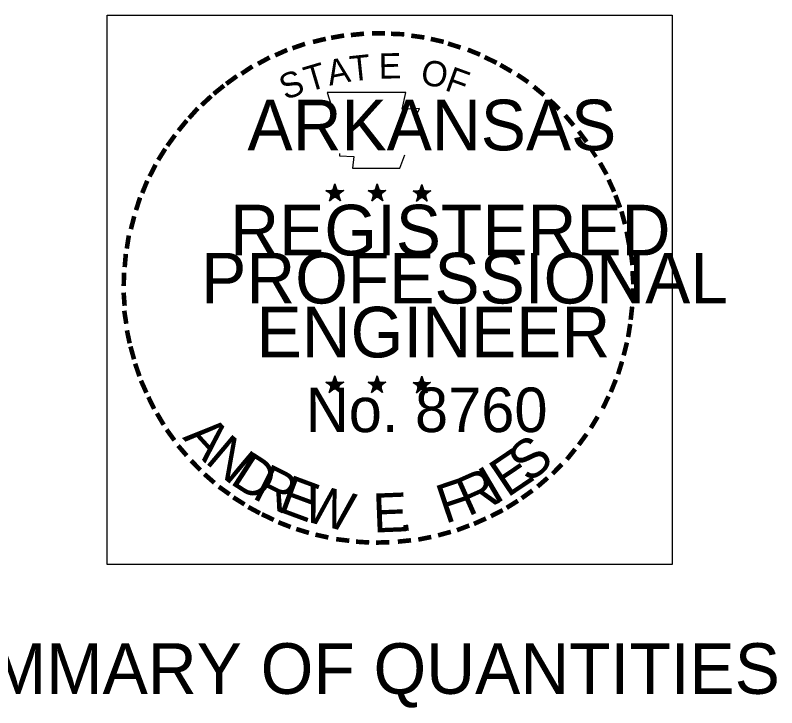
# Model space of a CAD drawing. Extents: x 1226603 to 1228117, y 151305 to 152343.
# Drawn here: x 1227929.3 to 1228117.2, y 151304.9 to 151475.9 of the extents above; entities that cross this region are included whole.
import ezdxf

# ---------------------------------------------------------------- set-up
doc = ezdxf.new("R2010")
doc.units = 0
for name, color, linetype in [('R_Border Notes', 7, 'Continuous'), ('R_Border PE', 7, 'Continuous'), ('R_Border Prem', 7, 'Continuous')]:
    doc.layers.add(name, color=color, linetype=linetype)

msp = doc.modelspace()

# ---------------------------------------------------------------- linework, layer by layer
at = {"layer": 'R_Border PE'}
for p, q in [((1228008.15, 151434.21), (1228007.83, 151432.64)), ((1228008.15, 151434.21), (1228007.9, 151432.58)), ((1228008.15, 151434.21), (1228008.08, 151432.64)), ((1228008.15, 151431.89), (1228008.15, 151434.21)), ((1228008.15, 151434.21), (1228008.58, 151432.58)), ((1228008.15, 151434.21), (1228008.46, 151432.64)), ((1228008.15, 151434.21), (1228008.33, 151432.64)), ((1228018.58, 151434.21), (1228018.27, 151432.64)), ((1228018.58, 151434.21), (1228018.33, 151432.58)), ((1228018.58, 151434.21), (1228018.46, 151432.64)), ((1228018.58, 151431.89), (1228018.58, 151434.21)), ((1228018.58, 151434.21), (1228019.02, 151432.58)), ((1228018.58, 151434.21), (1228018.9, 151432.64)), ((1228018.58, 151434.21), (1228018.71, 151432.64)), ((1228029.65, 151434.08), (1228029.27, 151432.58)), ((1228029.65, 151434.08), (1228029.4, 151432.52)), ((1228029.65, 151434.08), (1228029.52, 151432.52)), ((1228029.65, 151431.83), (1228029.65, 151434.08)), ((1228029.65, 151434.08), (1228030.08, 151432.52)), ((1228029.65, 151434.08), (1228029.96, 151432.52)), ((1228029.65, 151434.08), (1228029.77, 151432.58)), ((1228005.96, 151432.58), (1228008.15, 151431.89)), ((1228005.96, 151432.58), (1228007.58, 151432.46)), ((1228005.96, 151432.58), (1228007.58, 151432.33)), ((1228005.96, 151432.58), (1228007.52, 151432.21)), ((1228005.96, 151432.58), (1228007.52, 151431.96)), ((1228005.96, 151432.58), (1228007.46, 151431.83)), ((1228005.96, 151432.58), (1228007.46, 151431.71)), ((1228006.83, 151430.02), (1228008.15, 151431.89)), ((1228010.33, 151432.58), (1228008.15, 151431.89)), ((1228009.52, 151430.02), (1228008.15, 151431.89)), ((1228010.33, 151432.58), (1228008.4, 151432.46)), ((1228010.33, 151432.58), (1228008.52, 151432.27)), ((1228010.33, 151432.58), (1228008.52, 151432.14)), ((1228009.52, 151430.02), (1228008.77, 151431.89)), ((1228010.33, 151432.58), (1228008.96, 151432.02)), ((1228010.33, 151432.58), (1228009.08, 151431.96)), ((1228010.33, 151432.58), (1228009.15, 151431.89)), ((1228016.4, 151432.58), (1228018.58, 151431.89)), ((1228016.4, 151432.58), (1228018.02, 151432.46)), ((1228016.4, 151432.58), (1228018.02, 151432.33)), ((1228016.4, 151432.58), (1228017.96, 151432.21)), ((1228016.4, 151432.58), (1228017.9, 151431.96)), ((1228016.4, 151432.58), (1228017.9, 151431.83)), ((1228016.4, 151432.58), (1228017.9, 151431.71)), ((1228017.27, 151430.02), (1228018.58, 151431.89)), ((1228020.77, 151432.58), (1228018.58, 151431.89)), ((1228019.96, 151430.02), (1228018.58, 151431.89)), ((1228020.77, 151432.58), (1228018.83, 151432.46)), ((1228020.77, 151432.58), (1228018.96, 151432.27)), ((1228020.77, 151432.58), (1228018.96, 151432.14)), ((1228019.96, 151430.02), (1228019.21, 151431.89)), ((1228020.77, 151432.58), (1228019.4, 151432.02)), ((1228020.77, 151432.58), (1228019.52, 151431.96)), ((1228020.77, 151432.58), (1228019.58, 151431.89)), ((1228027.46, 151432.52), (1228029.65, 151431.83)), ((1228027.46, 151432.52), (1228029.08, 151432.33)), ((1228027.46, 151432.52), (1228029.02, 151432.21)), ((1228027.46, 151432.52), (1228029.02, 151432.14)), ((1228027.46, 151432.52), (1228028.96, 151431.89)), ((1228027.46, 151432.52), (1228028.96, 151431.77)), ((1228027.46, 151432.52), (1228028.96, 151431.64)), ((1228031.83, 151432.52), (1228029.65, 151431.83)), ((1228031.83, 151432.52), (1228029.9, 151432.39)), ((1228031.83, 151432.52), (1228030.02, 151432.21)), ((1228031.83, 151432.52), (1228030.02, 151432.08)), ((1228031.83, 151432.52), (1228030.46, 151431.96)), ((1228031.83, 151432.52), (1228030.52, 151431.89)), ((1228031.83, 151432.52), (1228030.65, 151431.83)), ((1228006.83, 151430.02), (1228007.52, 151431.77)), ((1228006.83, 151430.02), (1228007.58, 151431.58)), ((1228006.83, 151430.02), (1228007.71, 151431.52)), ((1228006.83, 151430.02), (1228008.15, 151431.39)), ((1228006.83, 151430.02), (1228007.9, 151431.33)), ((1228006.83, 151430.02), (1228008.21, 151431.21)), ((1228009.52, 151430.02), (1228008.15, 151431.39)), ((1228009.52, 151430.02), (1228008.15, 151431.21)), ((1228009.52, 151430.02), (1228008.4, 151431.33)), ((1228009.52, 151430.02), (1228008.58, 151431.58)), ((1228009.52, 151430.02), (1228008.65, 151431.83)), ((1228017.27, 151430.02), (1228017.96, 151431.77)), ((1228017.27, 151430.02), (1228018.02, 151431.58)), ((1228017.27, 151430.02), (1228018.15, 151431.52)), ((1228017.27, 151430.02), (1228018.58, 151431.39)), ((1228017.27, 151430.02), (1228018.33, 151431.33)), ((1228017.27, 151430.02), (1228018.65, 151431.21)), ((1228019.96, 151430.02), (1228018.58, 151431.39)), ((1228019.96, 151430.02), (1228018.58, 151431.21)), ((1228019.96, 151430.02), (1228018.83, 151431.33)), ((1228019.96, 151430.02), (1228019.02, 151431.58)), ((1228019.96, 151430.02), (1228019.08, 151431.83)), ((1228028.27, 151429.96), (1228029.65, 151431.83)), ((1228028.27, 151429.96), (1228029.02, 151431.71)), ((1228028.27, 151429.96), (1228029.08, 151431.52)), ((1228028.27, 151429.96), (1228029.21, 151431.46)), ((1228028.27, 151429.96), (1228029.65, 151431.33)), ((1228028.27, 151429.96), (1228029.4, 151431.27)), ((1228028.27, 151429.96), (1228029.71, 151431.14)), ((1228030.96, 151429.96), (1228029.65, 151431.83)), ((1228030.96, 151429.96), (1228029.65, 151431.33)), ((1228030.96, 151429.96), (1228029.65, 151431.14)), ((1228030.96, 151429.96), (1228029.9, 151431.27)), ((1228030.96, 151429.96), (1228030.08, 151431.52)), ((1228030.96, 151429.96), (1228030.15, 151431.77)), ((1228030.96, 151429.96), (1228030.27, 151431.77)), ((1228008.15, 151386.83), (1228007.77, 151385.33)), ((1228008.15, 151386.83), (1228007.9, 151385.27)), ((1228008.15, 151386.83), (1228008.02, 151385.27)), ((1228008.15, 151384.58), (1228008.15, 151386.83)), ((1228008.15, 151386.83), (1228008.58, 151385.27)), ((1228008.15, 151386.83), (1228008.46, 151385.27)), ((1228008.15, 151386.83), (1228008.27, 151385.27)), ((1228018.58, 151386.83), (1228018.21, 151385.33)), ((1228018.58, 151386.83), (1228018.33, 151385.27)), ((1228018.58, 151386.83), (1228018.46, 151385.27)), ((1228018.58, 151384.58), (1228018.58, 151386.83)), ((1228018.58, 151386.83), (1228018.96, 151385.27)), ((1228018.58, 151386.83), (1228018.9, 151385.27)), ((1228018.58, 151386.83), (1228018.71, 151385.27)), ((1228029.65, 151386.77), (1228029.27, 151385.21)), ((1228029.65, 151386.77), (1228029.4, 151385.21)), ((1228029.65, 151386.77), (1228029.52, 151385.21)), ((1228029.65, 151384.52), (1228029.65, 151386.77)), ((1228029.65, 151386.77), (1228030.02, 151385.21)), ((1228029.65, 151386.77), (1228029.96, 151385.21)), ((1228029.65, 151386.77), (1228029.77, 151385.21)), ((1228005.96, 151385.27), (1228008.15, 151384.58)), ((1228005.96, 151385.27), (1228007.58, 151385.08)), ((1228005.96, 151385.27), (1228007.52, 151384.96)), ((1228005.96, 151385.27), (1228007.52, 151384.89)), ((1228005.96, 151385.27), (1228007.46, 151384.64)), ((1228005.96, 151385.27), (1228007.46, 151384.52)), ((1228005.96, 151385.27), (1228007.46, 151384.39)), ((1228010.33, 151385.27), (1228008.15, 151384.58)), ((1228010.33, 151385.27), (1228008.4, 151385.14)), ((1228010.33, 151385.27), (1228008.52, 151384.96)), ((1228010.33, 151385.27), (1228008.52, 151384.83)), ((1228010.33, 151385.27), (1228008.9, 151384.71)), ((1228010.33, 151385.27), (1228009.02, 151384.64)), ((1228010.33, 151385.27), (1228009.15, 151384.52)), ((1228016.4, 151385.27), (1228018.58, 151384.58)), ((1228016.4, 151385.27), (1228017.96, 151385.08)), ((1228016.4, 151385.27), (1228017.96, 151384.96)), ((1228016.4, 151385.27), (1228017.96, 151384.89)), ((1228016.4, 151385.27), (1228017.9, 151384.64)), ((1228016.4, 151385.27), (1228017.9, 151384.52)), ((1228016.4, 151385.27), (1228017.9, 151384.39)), ((1228020.71, 151385.27), (1228018.58, 151384.58)), ((1228020.71, 151385.27), (1228018.83, 151385.14)), ((1228020.71, 151385.27), (1228018.96, 151384.96)), ((1228020.71, 151385.27), (1228018.96, 151384.83)), ((1228020.71, 151385.27), (1228019.33, 151384.71)), ((1228020.71, 151385.27), (1228019.46, 151384.64)), ((1228020.71, 151385.27), (1228019.58, 151384.52)), ((1228027.46, 151385.21), (1228029.65, 151384.52)), ((1228027.46, 151385.21), (1228029.02, 151385.02)), ((1228027.46, 151385.21), (1228029.02, 151384.89)), ((1228027.46, 151385.21), (1228028.96, 151384.77)), ((1228027.46, 151385.21), (1228028.96, 151384.58)), ((1228027.46, 151385.21), (1228028.9, 151384.39)), ((1228027.46, 151385.21), (1228028.9, 151384.27)), ((1228031.77, 151385.21), (1228029.65, 151384.52)), ((1228031.77, 151385.21), (1228029.9, 151385.08)), ((1228031.77, 151385.21), (1228030.02, 151384.89)), ((1228031.77, 151385.21), (1228030.02, 151384.77)), ((1228031.77, 151385.21), (1228030.4, 151384.64)), ((1228031.77, 151385.21), (1228030.52, 151384.52)), ((1228031.77, 151385.21), (1228030.58, 151384.46)), ((1228006.77, 151382.71), (1228008.15, 151384.58)), ((1228006.77, 151382.71), (1228007.52, 151384.46)), ((1228006.77, 151382.71), (1228007.58, 151384.21)), ((1228006.77, 151382.71), (1228007.71, 151384.14)), ((1228006.77, 151382.71), (1228008.15, 151384.08)), ((1228006.77, 151382.71), (1228007.9, 151384.02)), ((1228006.77, 151382.71), (1228008.15, 151383.89)), ((1228009.46, 151382.71), (1228008.08, 151383.89)), ((1228009.46, 151382.71), (1228008.15, 151384.58)), ((1228009.46, 151382.71), (1228008.15, 151384.02)), ((1228009.46, 151382.71), (1228008.33, 151384.02)), ((1228009.46, 151382.71), (1228008.58, 151384.52)), ((1228009.46, 151382.71), (1228008.58, 151384.27)), ((1228009.46, 151382.71), (1228008.77, 151384.52)), ((1228017.21, 151382.71), (1228018.58, 151384.58)), ((1228017.21, 151382.71), (1228017.96, 151384.46)), ((1228017.21, 151382.71), (1228018.02, 151384.21)), ((1228017.21, 151382.71), (1228018.15, 151384.14)), ((1228017.21, 151382.71), (1228018.58, 151384.08)), ((1228017.21, 151382.71), (1228018.33, 151384.02)), ((1228017.21, 151382.71), (1228018.58, 151383.89)), ((1228019.9, 151382.71), (1228018.52, 151383.89)), ((1228019.9, 151382.71), (1228018.58, 151384.58)), ((1228019.9, 151382.71), (1228018.58, 151384.02)), ((1228019.9, 151382.71), (1228018.77, 151384.02)), ((1228019.9, 151382.71), (1228019.02, 151384.52)), ((1228019.9, 151382.71), (1228019.02, 151384.27)), ((1228019.9, 151382.71), (1228019.21, 151384.52)), ((1228028.27, 151382.64), (1228029.65, 151384.52)), ((1228028.27, 151382.64), (1228028.96, 151384.39)), ((1228028.27, 151382.64), (1228029.02, 151384.14)), ((1228028.27, 151382.64), (1228029.21, 151384.08)), ((1228028.27, 151382.64), (1228029.4, 151383.96)), ((1228028.27, 151382.64), (1228029.58, 151383.96)), ((1228028.27, 151382.64), (1228029.65, 151383.83)), ((1228030.96, 151382.64), (1228029.58, 151383.96)), ((1228030.96, 151382.64), (1228029.58, 151383.77)), ((1228030.96, 151382.64), (1228029.65, 151384.52)), ((1228030.96, 151382.64), (1228029.83, 151383.96)), ((1228030.96, 151382.64), (1228030.02, 151384.14)), ((1228030.96, 151382.64), (1228030.08, 151384.46)), ((1228030.96, 151382.64), (1228030.21, 151384.46))]:
    msp.add_line(p, q, dxfattribs=at)
for points in [[(1228006.27, 151456.83), (1228007.9, 151451.64)], [(1228028.21, 151451.08), (1228029.08, 151452.83), (1228024.77, 151452.71), (1228025.71, 151456.83), (1228006.27, 151456.83)], [(1228009.33, 151441.71), (1228009.33, 151441.14), (1228012.83, 151441.02), (1228012.52, 151438.08), (1228024.21, 151438.08), (1228025.46, 151441.39)], [(1228008.15, 151434.21), (1228009.52, 151430.02), (1228005.96, 151432.58), (1228010.33, 151432.58), (1228006.83, 151430.02), (1228008.15, 151434.21)], [(1228018.58, 151434.21), (1228019.96, 151430.02), (1228016.4, 151432.58), (1228020.77, 151432.58), (1228017.27, 151430.02), (1228018.58, 151434.21)], [(1228029.65, 151434.08), (1228030.96, 151429.96), (1228027.46, 151432.52), (1228031.83, 151432.52), (1228028.27, 151429.96), (1228029.65, 151434.08)], [(1228008.15, 151386.83), (1228009.46, 151382.71), (1228005.96, 151385.27), (1228010.33, 151385.27), (1228006.77, 151382.71), (1228008.15, 151386.83)], [(1228018.58, 151386.83), (1228019.9, 151382.71), (1228016.4, 151385.27), (1228020.71, 151385.27), (1228017.21, 151382.71), (1228018.58, 151386.83)], [(1228029.65, 151386.77), (1228030.96, 151382.64), (1228027.46, 151385.21), (1228031.77, 151385.21), (1228028.27, 151382.64), (1228029.65, 151386.77)]]:
    msp.add_lwpolyline(points, dxfattribs=at)
for centre, radius in [((1228008.17, 151431.89), 1.08), ((1228008.17, 151431.89), 0.975), ((1228008.17, 151431.89), 0.904), ((1228008.17, 151431.89), 0.83), ((1228008.17, 151431.89), 0.723), ((1228008.17, 151431.89), 0.672), ((1228008.17, 151431.89), 0.619), ((1228008.17, 151431.89), 0.533), ((1228008.17, 151431.89), 0.467), ((1228008.17, 151431.89), 0.388), ((1228008.17, 151431.89), 0.31), ((1228008.17, 151431.89), 0.231), ((1228008.17, 151431.89), 0.185), ((1228008.17, 151431.89), 0.0901), ((1228018.6, 151431.89), 1.08), ((1228018.6, 151431.89), 0.975), ((1228018.6, 151431.89), 0.904), ((1228018.6, 151431.89), 0.83), ((1228018.6, 151431.89), 0.723), ((1228018.6, 151431.89), 0.672), ((1228018.6, 151431.89), 0.619), ((1228018.6, 151431.89), 0.533), ((1228018.6, 151431.89), 0.467), ((1228018.6, 151431.89), 0.388), ((1228018.6, 151431.89), 0.31), ((1228018.6, 151431.89), 0.231), ((1228018.6, 151431.89), 0.185), ((1228018.6, 151431.89), 0.0901), ((1228029.64, 151431.81), 1.08), ((1228029.64, 151431.81), 0.975), ((1228029.64, 151431.81), 0.904), ((1228029.64, 151431.81), 0.83), ((1228029.64, 151431.81), 0.723), ((1228029.64, 151431.81), 0.672), ((1228029.64, 151431.81), 0.619), ((1228029.64, 151431.81), 0.533), ((1228029.64, 151431.81), 0.467), ((1228029.64, 151431.81), 0.388), ((1228029.64, 151431.81), 0.31), ((1228029.64, 151431.81), 0.231), ((1228029.64, 151431.81), 0.185), ((1228029.64, 151431.81), 0.0901), ((1228008.14, 151384.56), 1.08), ((1228008.14, 151384.56), 0.975), ((1228008.14, 151384.56), 0.904), ((1228008.14, 151384.56), 0.83), ((1228008.14, 151384.56), 0.723), ((1228008.14, 151384.56), 0.672), ((1228008.14, 151384.56), 0.619), ((1228008.14, 151384.56), 0.533), ((1228008.14, 151384.56), 0.467), ((1228008.14, 151384.56), 0.388), ((1228018.57, 151384.56), 1.08), ((1228018.57, 151384.56), 0.975), ((1228018.57, 151384.56), 0.904), ((1228018.57, 151384.56), 0.83), ((1228018.57, 151384.56), 0.723), ((1228018.57, 151384.56), 0.672), ((1228018.57, 151384.56), 0.619), ((1228018.57, 151384.56), 0.533), ((1228018.57, 151384.56), 0.467), ((1228018.57, 151384.56), 0.388), ((1228029.62, 151384.48), 1.08), ((1228029.62, 151384.48), 0.975), ((1228029.62, 151384.48), 0.904), ((1228029.62, 151384.48), 0.83), ((1228029.62, 151384.48), 0.723), ((1228029.62, 151384.48), 0.672), ((1228029.62, 151384.48), 0.619), ((1228029.62, 151384.48), 0.533), ((1228029.62, 151384.48), 0.467), ((1228008.14, 151384.56), 0.31), ((1228008.14, 151384.56), 0.231), ((1228008.14, 151384.56), 0.185), ((1228008.14, 151384.56), 0.0901), ((1228018.57, 151384.56), 0.31), ((1228018.57, 151384.56), 0.231), ((1228018.57, 151384.56), 0.185), ((1228018.57, 151384.56), 0.0901), ((1228029.62, 151384.48), 0.388), ((1228029.62, 151384.48), 0.31), ((1228029.62, 151384.48), 0.231), ((1228029.62, 151384.48), 0.185), ((1228029.62, 151384.48), 0.0901)]:
    msp.add_circle(centre, radius, dxfattribs=at)
at = {"layer": 'R_Border Prem'}
msp.add_lwpolyline([(1227951.93, 151475.88), (1228091.43, 151475.88), (1228091.43, 151340.25), (1227951.93, 151340.25)], close=True, dxfattribs=at)

# ---------------------------------------------------------------- texts
at = {"layer": 'R_Border Notes'}
msp.add_text('SUMMARY OF QUANTITIES', height=12.5, dxfattribs=at).set_placement((1227899.76, 151308.33))
at = {"layer": 'R_Border PE'}
for s, height, rotation, p in [('-', 10, 10.2193, (1228007.33, 151466.39)), ('-', 10, 5.8968, (1228011.9, 151467.08)), ('-', 10, 0.1862, (1228016.71, 151467.52)), ('-', 10, 357.743, (1228021.27, 151467.46)), ('-', 10, 352.1617, (1228025.9, 151467.08)), ('-', 10, 13.6302, (1228003.08, 151465.39)), ('-', 10, 347.2049, (1228030.4, 151466.39)), ('-', 10, 24.3072, (1227994.46, 151462.21)), ('-', 10, 19.1761, (1227998.4, 151463.89)), ('-', 10, 342.3362, (1228034.33, 151465.39)), ('-', 10, 337.8551, (1228038.96, 151464.02)), ('-', 10, 28.7918, (1227990.52, 151460.21)), ('T', 6.25, 6.0228, (1228012.15, 151459.52)), ('E', 6.25, 0.8323, (1228019.02, 151460.21)), ('-', 10, 334.1211, (1228042.9, 151462.33)), ('T', 6.25, 16.4036, (1228001.65, 151456.89)), ('A', 6.25, 11.2132, (1228006.83, 151458.46)), ('O', 6.25, 350.4515, (1228029.08, 151458.89)), ('-', 10, 329.6409, (1228046.52, 151460.58)), ('-', 10, 34.0636, (1227986.77, 151457.89)), ('S', 6.25, 21.594, (1227995.96, 151454.83)), ('F', 6.25, 340.0707, (1228035.02, 151457.46)), ('-', 10, 36.2317, (1227983.15, 151455.46)), ('-', 10, 325.8627, (1228050.52, 151458.33)), ('-', 10, 38.9507, (1227980.21, 151453.08)), ('-', 10, 320.5297, (1228054.33, 151455.64)), ('-', 10, 42.9622, (1227977.46, 151450.46)), ('-', 10, 315.5786, (1228058.08, 151452.58)), ('-', 10, 48.423, (1227974.65, 151447.46)), ('-', 10, 309.8797, (1228061.65, 151449.14)), ('-', 10, 50.6142, (1227972.15, 151444.46)), ('-', 10, 306.6522, (1228064.9, 151445.39)), ('-', 10, 54.2325, (1227969.58, 151440.89)), ('-', 10, 58.0706, (1227967.52, 151437.58)), ('-', 8.75, 303.6753, (1228067.96, 151441.83)), ('-', 10, 299.6684, (1228069.96, 151438.02)), ('-', 10, 62.8713, (1227965.58, 151433.77)), ('-', 10, 67.7743, (1227963.96, 151429.96)), ('-', 10, 294.6628, (1228071.96, 151434.21)), ('-', 10, 72.3945, (1227962.58, 151426.02)), ('-', 10, 290.5728, (1228073.58, 151430.64)), ('-', 10, 75.461, (1227961.4, 151421.52)), ('-', 10, 285.1233, (1228075.02, 151427.02)), ('-', 10, 280.5493, (1228076.27, 151422.33)), ('-', 10, 81.2013, (1227960.52, 151417.08)), ('-', 10, 85.1863, (1227960.08, 151412.77)), ('-', 10, 276.5962, (1228077.33, 151417.58)), ('-', 10, 89.0622, (1227959.9, 151408.39)), ('-', 10, 274.3301, (1228077.71, 151413.02)), ('-', 10, 94.1959, (1227960.15, 151403.83)), ('-', 10, 269.9407, (1228077.9, 151409.08)), ('-', 10, 263.5172, (1228077.77, 151404.96)), ('-', 10, 98.9479, (1227960.58, 151399.71)), ('-', 10, 101.7149, (1227961.4, 151395.08)), ('-', 10, 260.9953, (1228077.33, 151400.83)), ('-', 10, 255.7626, (1228076.65, 151396.58)), ('-', 10, 105.4578, (1227962.46, 151391.39)), ('-', 10, 252.8681, (1228075.52, 151392.08)), ('-', 10, 109.0874, (1227963.77, 151387.46)), ('-', 10, 114.0643, (1227965.4, 151383.71)), ('-', 10, 247.8887, (1228074.15, 151387.89)), ('-', 10, 115.7289, (1227967.27, 151379.83)), ('-', 10, 244.6197, (1228072.46, 151383.96)), ('-', 10, 120.4471, (1227969.52, 151376.21)), ('-', 10, 239.0712, (1228070.02, 151379.27)), ('-', 10, 125.8934, (1227972.02, 151372.71)), ('A', 9.62, 312.4727, (1227970.4, 151371.51)), ('N', 9.62, 319.8362, (1227975.83, 151365.58)), ('-', 10, 233.8452, (1228067.52, 151375.21)), ('-', 10, 130.7181, (1227974.9, 151369.21)), ('S', 9.62, 39.723, (1228056.06, 151360.11)), ('E', 9.62, 33.8878, (1228050.72, 151356.63)), ('-', 10, 231.2538, (1228064.83, 151371.64)), ('-', 10, 134.2238, (1227978.15, 151365.83)), ('D', 9.62, 327.1996, (1227981.98, 151360.39)), ('R', 9.62, 333.1738, (1227987.42, 151356.79)), ('I', 9.62, 30.5534, (1228047.52, 151354.89)), ('-', 10, 225.7653, (1228061.83, 151368.14)), ('-', 10, 138.9338, (1227981.4, 151362.96)), ('R', 9.62, 24.0235, (1228040.99, 151352.03)), ('E', 9.62, 339.7037, (1227993.76, 151353.53)), ('W', 9.62, 345.5389, (1227999.71, 151351.23)), ('F', 9.62, 18.6051, (1228035.34, 151350.24)), ('-', 10, 221.0851, (1228058.58, 151364.96)), ('-', 10, 144.6463, (1227984.9, 151360.39)), ('-', 10, 215.7363, (1228055.15, 151362.02)), ('-', 10, 148.0898, (1227988.4, 151358.08)), ('E', 9.62, 2.2804, (1228017.68, 151348.14)), ('-', 10, 151.5704, (1227992.02, 151356.02)), ('-', 10, 212.2491, (1228051.77, 151359.58)), ('-', 10, 154.6002, (1227995.27, 151354.52)), ('-', 10, 207.3568, (1228048.33, 151357.39)), ('-', 10, 158.5612, (1227999.21, 151352.89)), ('-', 10, 204.2516, (1228044.4, 151355.39)), ('-', 10, 162.7983, (1228003.46, 151351.58)), ('.', 9.62, 8.1156, (1228024.06, 151348.31)), ('-', 10, 200.7184, (1228040.52, 151353.71)), ('-', 10, 167.5555, (1228007.96, 151350.58)), ('-', 10, 191.2858, (1228031.77, 151350.96)), ('-', 10, 195.4743, (1228036.33, 151352.21)), ('-', 10, 173.1155, (1228012.77, 151349.89)), ('-', 10, 176.5183, (1228017.46, 151349.52)), ('-', 10, 181.5918, (1228022.08, 151349.64)), ('-', 10, 185.8167, (1228027.15, 151350.14))]:
    msp.add_text(s, height=height, rotation=rotation, dxfattribs=at).set_placement(p)
for s, height, p in [('ARKANSAS', 12.5, (1227986.58, 151442.52)), ('REGISTERED', 12.5, (1227982.33, 151416.58)), ('PROFESSIONAL', 12.4999, (1227975.15, 151404.71)), ('ENGINEER', 12.5, (1227988.83, 151391.39)), ('No. 8760', 11, (1228000.95, 151372.96))]:
    msp.add_text(s, height=height, dxfattribs=at).set_placement(p)

doc.saveas('drawing.dxf')
